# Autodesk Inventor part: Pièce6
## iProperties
Created: 2009-06
Part Number: Pièce6
Document SubType Name: Modeling
Designer: ajtco
Manufacturer: Standard
Standards Organization: Custom
Author: ajtco
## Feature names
1. Extrusion1
